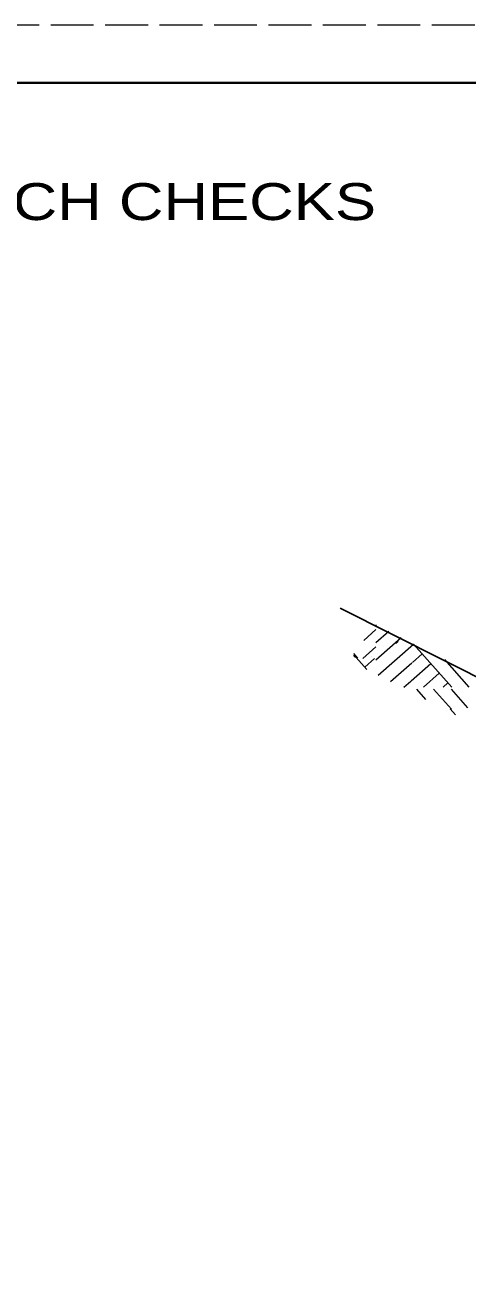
# Model space of a CAD drawing. Extents: x 1083.1 to 1117.1, y 672.5 to 716.5.
# Drawn here: x 1100.48 to 1104.32, y 705.66 to 716.51 of the extents above; entities that cross this region are included whole.
import ezdxf
from ezdxf.enums import TextEntityAlignment as Align

# ---------------------------------------------------------------- set-up
doc = ezdxf.new("R2010")
doc.units = 0
doc.header["$LTSCALE"] = 0.062
doc.linetypes.add('LONG_DASHED', pattern=[7.5, 6, -1.5])
doc.layers.add('1', color=7, linetype='Continuous', lineweight=13)

msp = doc.modelspace()

# ---------------------------------------------------------------- linework, layer by layer
at = {"layer": '1', "lineweight": 25}
for p, q in [((1085.12642, 716.00825), (1116.62642, 716.00825)), ((1107.81192, 709.13767), (1103.21475, 711.45358))]:
    msp.add_line(p, q, dxfattribs=at)
at = {"layer": '1'}
for p, q in [((1103.41975, 711.173), (1103.526, 711.267)), ((1103.526, 711.30425), (1103.52917, 711.30708)), ((1103.526, 711.15392), (1103.63725, 711.25225)), ((1103.41358, 711.017), (1103.526, 711.11642)), ((1103.526, 711.00392), (1103.74508, 711.1975)), ((1103.54517, 710.87092), (1103.85133, 711.1415)), ((1103.69917, 711.15083), (1103.71883, 711.16833)), ((1103.85133, 711.1415), (1104.18225, 710.76758)), ((1103.33142, 711.06025), (1103.36717, 711.01983)), ((1103.33217, 711.04358), (1103.34758, 711.02617)), ((1103.355, 711.025), (1103.44675, 710.92125)), ((1103.4295, 710.94075), (1103.51367, 711.01525)), ((1103.49125, 711.03367), (1103.4915, 711.03342)), ((1103.84167, 710.98283), (1103.92583, 711.05733)), ((1104.12042, 711.00708), (1104.33233, 710.76758)), ((1103.65267, 710.81592), (1103.83825, 710.98)), ((1103.83192, 710.82392), (1104.00058, 710.97308)), ((1103.93792, 710.76758), (1104.07508, 710.88892)), ((1103.76825, 710.76758), (1103.8285, 710.82083)), ((1104.10783, 710.76758), (1104.14958, 710.80475)), ((1103.87608, 710.751), (1103.95575, 710.66083)), ((1104.02608, 710.75117), (1104.18, 710.57708)), ((1104.17658, 710.75117), (1104.32, 710.58892)), ((1104.16875, 710.581), (1104.216, 710.52767))]:
    msp.add_line(p, q, dxfattribs=at)
at = {"layer": '1', "linetype": 'LONG_DASHED'}
msp.add_lwpolyline([(1083.12642, 694.50825), (1117.12642, 694.50825), (1117.12642, 716.50825), (1083.12642, 716.50825)], close=True, dxfattribs=at)
at = {"layer": '1', "lineweight": 40}
msp.add_lwpolyline([(1085.12642, 716.00825), (1116.62642, 716.00825), (1116.62642, 695.00825), (1085.12642, 695.00825)], close=True, dxfattribs=at)
msp.add_lwpolyline([(1085.12642, 716.00825), (1116.62642, 716.00825), (1116.62642, 695.00825), (1085.12642, 695.00825)], close=True, dxfattribs=at)

# ---------------------------------------------------------------- texts
at = {"layer": '1', "width": 1.25}
msp.add_text('DITCH CHECKS', height=0.32, dxfattribs=at).set_placement((1101.521, 714.81758), align=Align.CENTER)

doc.saveas('drawing.dxf')
